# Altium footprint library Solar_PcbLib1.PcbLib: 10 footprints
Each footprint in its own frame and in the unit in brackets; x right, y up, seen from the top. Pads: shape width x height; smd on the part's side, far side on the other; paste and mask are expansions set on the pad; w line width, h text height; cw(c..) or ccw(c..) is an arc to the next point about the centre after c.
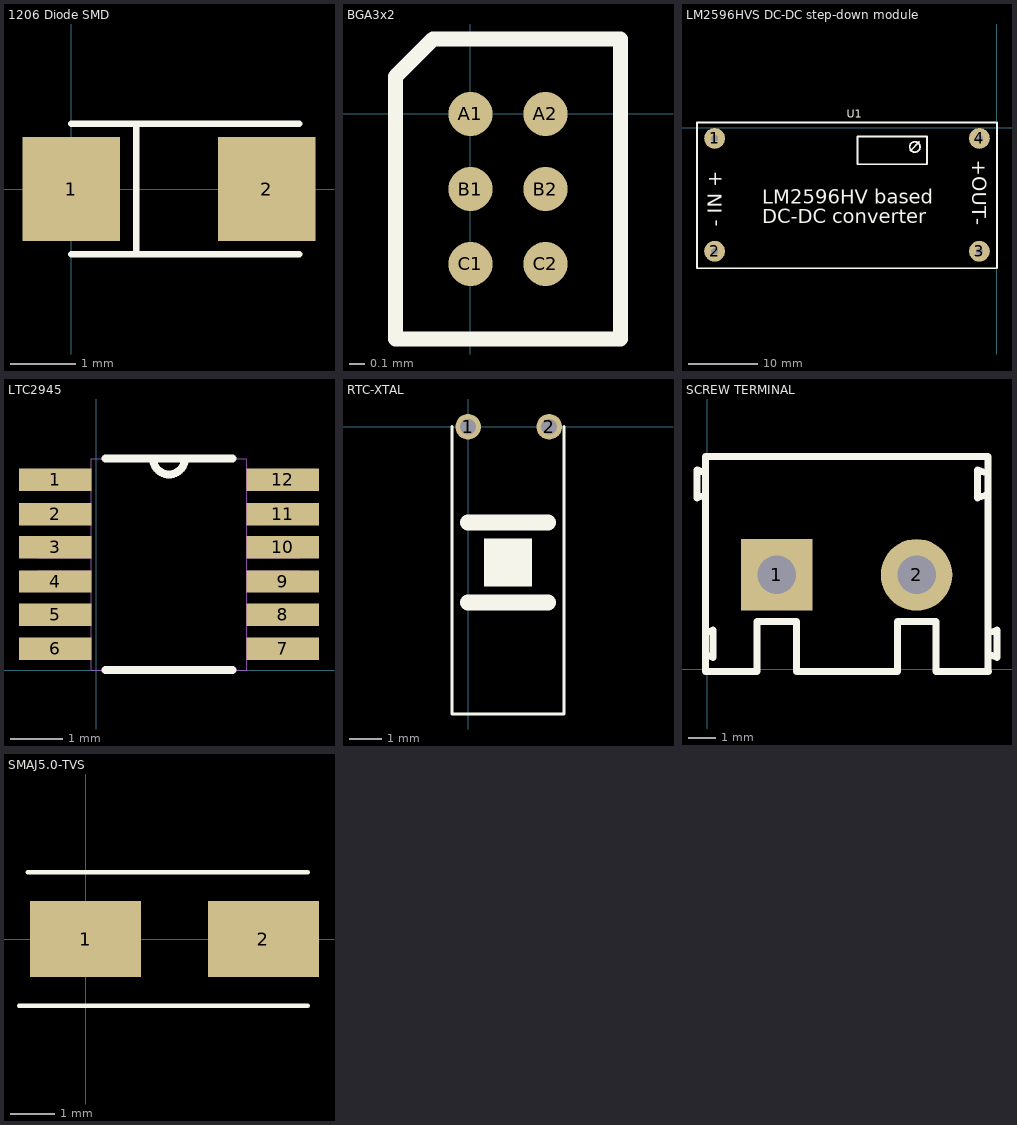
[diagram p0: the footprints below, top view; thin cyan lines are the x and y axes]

## 1206 Diode SMD [mm] "CD1206-S01575CT-ND"
pads (2):
  rect 1.5x1.6 smd: 1(0,0) 2(3,0)
Top Overlay:
  lines w0.1: 0,-1 3.5,-1 ; 0,1 3.5,1 ; 1,-1 1,1

## ADP119 [mil] "High-Side or Low-Side Load Switch"

## BGA3x2 [mm]
pads (6):
  round 0.295 smd: A1(0,0) A2(0.5,0) B1(0,-0.5) B2(0.5,-0.5) C1(0,-1) C2(0.5,-1)
Top Overlay:
  lines w0.1: -0.5,-1.5 -0.5,0.25 -0.25,0.5 1,0.5 1,-1.5 -0.5,-1.5

## LM2596 [mil] "Adjustable Buck Converter"

## LM2596HVS DC-DC step-down module [mm]
pads (4):
  round 3 hole 0.914 slot 0.96 at 0 deg: 1(-40.64,-1.524) 2(-40.64,-17.78) 3(-2.54,-17.78) 4(-2.54,-1.524)
Top Overlay:
  circle w0.254: c-11.816,-2.766 r0.749
  lines w0.254: -12.446,-3.302 -11.176,-2.032 ; -0.18,-20.238 -43.18,-20.238 -43.18,-17.78 -43.18,0.762 -0.18,0.762 ; 0,-20.238 0,-10.414 0,0.762 ; -20.066,-5.266 -20.066,-1.266 -10.066,-1.266 -10.066,-5.266 -20.066,-5.266
  text "U1" at -21.59,1.46 h1.14
  text "LM2596HV based" at -33.782,-10.922 h2.03
  text "DC-DC converter" at -33.782,-13.716 h2.03
  text "- IN +" at -39.624,-14.224 h2.03
  text "+OUT-" at -3.556,-4.572 h2.03

## LTC2945 [mil] "12MSOP"
pads (12):
  rect 55x17 smd: 1(-31,144) 2(-31,118) 3(-31,93) 4(-31,67) 5(-31,42) 6(-31,16) 7(141,16) 8(141,42) 9(141,67) 10(141,93) 11(141,118) 12(141,144)
Top Overlay:
  lines w6: 7,0 103,0 ; 7,160 43,160 ; 103,160 67,160 ; 43,160 ccw(c55,160) 67,160 ; 43,160 67,160
Mechanical 16:
  lines w0: 43,160 ccw(c55,160) 67,160 ; 43,160 -4,160 -4,0 114,0 114,160 67,160 ; 43,160 67,160 ; -44,9 -4,9 -4,23 -44,23 -44,9 ; -44,34 -4,34 -4,49 -44,49 -44,34 ; -44,60 -4,60 -4,75 -44,75 -44,60 ; -44,85 -4,85 -4,100 -44,100 -44,85 ; -44,111 -4,111 -4,126 -44,126 -44,111 ; -44,137 -4,137 -4,151 -44,151 -44,137 ; 114,9 154,9 154,23 114,23 114,9 ; 114,34 154,34 154,49 114,49 114,34 ; 114,60 154,60 154,75 114,75 114,60 ; 114,85 154,85 154,100 114,100 114,85 ; 114,111 154,111 154,126 114,126 114,111 ; 114,137 154,137 154,151 114,151 114,137

## PCBComponent_1 [mil]

## RTC-XTAL [mm] "RTC Crystal 32.768KHz"
pads (2):
  round 0.8 hole 0.5: 1(0,0) 2(2.54,0)
Top Overlay:
  rectangle: 0.5,-5 2,-3.5
  lines w0.1: -0.5,0 -0.5,-9 3,-9 3,0
  lines w0.5: 0,-5.5 2.5,-5.5 ; 0,-3 2.5,-3

## SCREW TERMINAL [mil] "PG Connector"
pads (2):
  rect 102.4x102.4 hole 55.2: 1(99.24,134.81)
  round 102.4 hole 55.2: 2(299.24,134.81)
Top Overlay:
  lines w10: -2.76,20.81 8.24,16.81 8.24,55.81 -2.76,51.81 ; 398.24,248.81 386.24,244.81 386.24,284.81 398.24,280.81 ; 401.24,-3.19 401.24,303.81 -2.76,303.81 -2.76,280.81 ; 402.24,-3.19 327.24,-3.19 327.24,67.81 272.24,67.81 272.24,-3.19 127.24,-3.19 127.24,67.81 71.24,67.81 71.24,-3.19 -2.76,-3.19 -2.76,248.81 ; 402.24,20.81 414.24,16.81 414.24,55.81 402.24,51.81 ; -2.76,248.81 -2.76,280.81 ; -2.76,248.81 -14.76,244.81 -14.76,284.81 -2.76,280.81

## SMAJ5.0-TVS [mm] "400W SURFACE MOUNT TRANSIENT VOLTAGE SUPPRESSOR"
pads (2):
  rect 2.5x1.7 smd: 1(0,0) 2(4,0)
Top Overlay:
  lines w0.1: -1.5,-1.5 5,-1.5 ; -1.3,1.5 5,1.5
